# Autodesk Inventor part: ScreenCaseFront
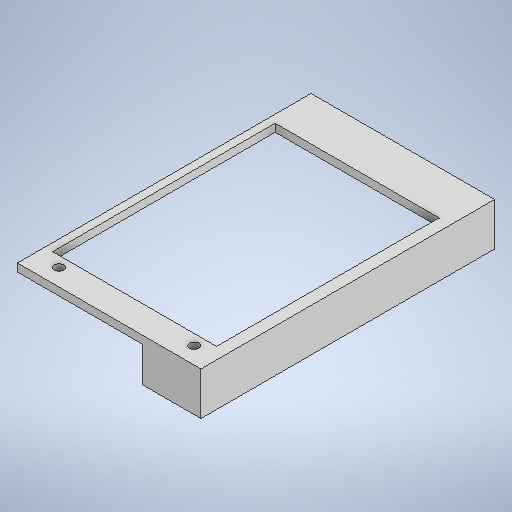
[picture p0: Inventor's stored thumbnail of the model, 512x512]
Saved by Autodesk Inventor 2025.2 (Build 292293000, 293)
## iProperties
Created: 2025-12
Part Number: ScreenCaseFront
Material: Generic
Document SubType Name: Modeling
Designer: tyler
Density: 1 g/cm^3
Appearance: Default
Author: tyler
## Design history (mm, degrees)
sketch "Sketch1"
  geometry: L1 (28.575, 47.752)-(-28.575, 47.752); L2 (-28.575, 47.752)-(-28.575, -47.752); L3 (-28.575, -47.752)-(28.575, -47.752); L4 (28.575, -47.752)-(28.575, 47.752); L5 (28.575, 47.752)-(-28.575, -47.752); L6 (-28.575, 47.752)-(28.575, -47.752); L7 (28.575, 38.862)-(-24.765, 38.862); L8 (-24.765, 38.862)-(-24.765, -33.528); L9 (-24.765, -33.528)-(28.575, -33.528); L10 (28.575, -33.528)-(28.575, 38.862); L11 (28.575, 38.862)-(-24.765, -33.528); L12 (-24.765, 38.862)-(28.575, -33.528); L13 (28.575, 47.752)-(31.115, 47.752); L14 (31.115, 47.752)-(31.115, -47.752); L15 (31.115, -47.752)-(28.575, -47.752); 4 further points
  constraints: 30 end point, 4 midpoint, 4 parallel, 4 perpendicular, 3 horizontal
  dimensions: "d0" = 57.15 distance of L3.end L2.end; "d1" = 95.504 distance of L2.end L1.end; "d2" = 53.34 distance of L9.end L8.end; "d3" = 72.39 distance of L8.end L7.end; "d4" = 8.89 distance between parallel lines of L7 L1; "d5" = 0 distance between parallel lines of L4 L10; "d24" = 2.54 distance of L1.start L13.end
extrude "Extrusion1" new body sketch "Sketch1" distance "d6" = 2.54; taper "d7" = 0 deg
sketch "Sketch2"
  geometry: L1 (-28.575, -38.862)-(-28.575, 33.528) reference; L2 (-28.575, -47.752)-(-28.575, -42.291); L3 (-28.575, -42.291)-(-23.114, -42.291); L4 (28.575, -47.752)-(28.575, 47.752) reference; L5 (28.575, -47.752)-(28.575, -42.291); L6 (28.575, -42.291)-(20.955, -42.291); C1 r 1.524 at (-23.114, -42.291); C2 r 1.524 at (20.955, -42.291); 1 further point
  constraints: 8 end point, 2 centre point, 2 coincident, 2 perpendicular, 2 point on line
  dimensions: "d8" = 5.461 distance of L2.start L2.end; "d9" = 5.461 distance of L2.end L3.end; "d10" = 3.048 diameter of C1; "d11" = 5.461 distance of L4.start L5.end; "d12" = 7.62 distance of L5.end L6.end; "d13" = 3.048 diameter of C2
extrude "Extrusion2" cut sketch "Sketch2" distance "d14" = 2.54; taper "d15" = 0 deg
sketch "Sketch3"
  geometry: L1 (-28.575, 47.752)-(28.575, 47.752) reference; L2 (28.575, 47.752)-(26.035, 47.752); L3 (26.035, 47.752)-(26.035, -47.752); L4 (28.575, -47.752)-(-31.115, -47.752) reference; L5 (28.575, 47.752)-(28.575, 45.212); L6 (28.575, 45.212)-(9.525, 45.212); L7 (9.525, 45.212)-(9.525, 47.752); L8 (28.575, -47.752)-(28.575, -46.482); L9 (28.575, 47.752)-(28.575, -47.752) reference; L10 (28.575, -46.482)-(-28.575, -46.482); L11 (-28.575, -46.482)-(-26.035, -46.482); L12 (-26.035, -46.482)-(-26.035, -47.752); 4 further points
  constraints: 18 end point, 6 point on line, 3 perpendicular, 1 horizontal, 1 vertical
  dimensions: "d16" = 2.54 distance of L1.end L2.end; "d17" = 90 deg angle of L3 L2; "d18" = 2.54 distance of L1.end L5.end; "d19" = 19.05 distance of L5.end L6.end; "d20" = 1.27 distance of L4.start L8.end; "d21" = 2.54 distance of L10.end L11.end
extrude "Extrusion3" join sketch "Sketch3" distance "d22" = 11.43; taper "d23" = 0 deg
body "Solid1"
